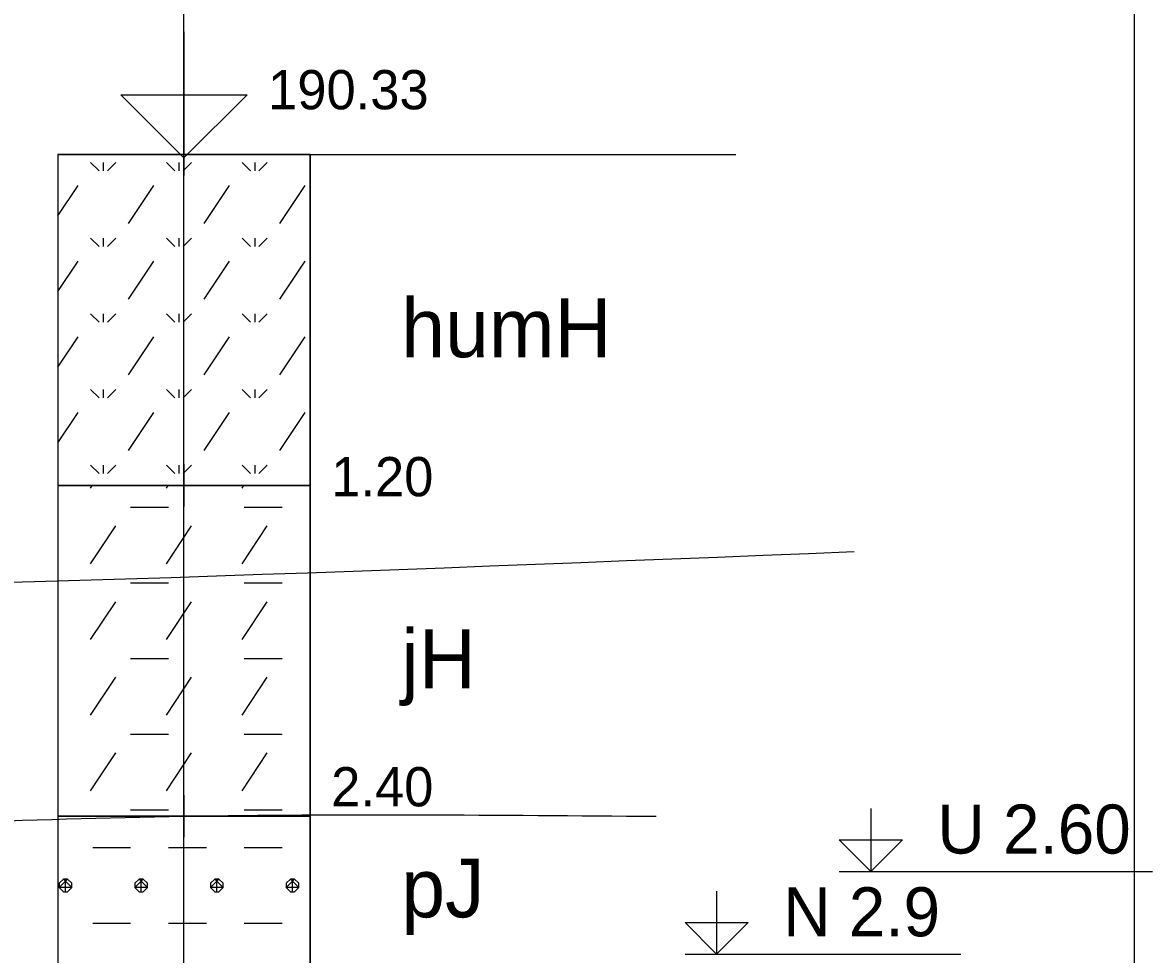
# Model space of a CAD drawing. Extents: x 3042 to 4120, y 576 to 2694.
# Drawn here: x 3544.97 to 3565.44, y 1293.69 to 1310.59 of the extents above; entities that cross this region are included whole.
import ezdxf

# ---------------------------------------------------------------- set-up
doc = ezdxf.new("R2010")
doc.units = 0
for name, color, linetype in [('11', 7, 'Continuous'), ('15', 7, 'Continuous'), ('17', 7, 'Continuous'), ('18', 7, 'Continuous'), ('51', 7, 'Continuous'), ('52', 7, 'Continuous'), ('53', 7, 'Continuous'), ('56', 7, 'Continuous'), ('61', 7, 'Continuous'), ('pomocna', 7, 'Continuous'), ('rozhraní', 7, 'Continuous')]:
    doc.layers.add(name, color=color, linetype=linetype)

msp = doc.modelspace()

# ---------------------------------------------------------------- linework, layer by layer
at = {"layer": '11'}
msp.add_line((3547.897, 1308.195), (3557.897, 1308.195), dxfattribs=at)
at = {"layer": '15'}
msp.add_lwpolyline([(3547.897, 1310.418), (3547.897, 1308.132), (3546.754, 1309.275), (3549.04, 1309.275), (3547.897, 1308.132)], dxfattribs=at)
msp.add_lwpolyline([(3547.897, 1310.418), (3547.897, 1308.132), (3546.754, 1309.275), (3549.04, 1309.275), (3547.897, 1308.132)], dxfattribs=at)
at = {"layer": '18'}
msp.add_line((3547.897, 1265.195), (3547.897, 1308.195), dxfattribs=at)
at = {"layer": '51'}
for p, q in [((3546.206, 1308.049), (3546.359, 1307.897)), ((3546.435, 1308.049), (3546.435, 1307.897)), ((3546.663, 1308.049), (3546.511, 1307.897)), ((3547.578, 1308.049), (3547.73, 1307.897)), ((3547.806, 1308.049), (3547.806, 1307.897)), ((3548.035, 1308.049), (3547.883, 1307.897)), ((3548.949, 1308.049), (3549.102, 1307.897)), ((3549.178, 1308.049), (3549.178, 1307.897)), ((3549.407, 1308.049), (3549.254, 1307.897)), ((3545.611, 1307.08), (3545.978, 1307.63)), ((3546.892, 1306.944), (3547.349, 1307.63)), ((3548.264, 1306.944), (3548.721, 1307.63)), ((3549.635, 1306.944), (3550.092, 1307.63)), ((3546.206, 1306.678), (3546.359, 1306.525)), ((3546.435, 1306.678), (3546.435, 1306.525)), ((3546.663, 1306.678), (3546.511, 1306.525)), ((3547.578, 1306.678), (3547.73, 1306.525)), ((3547.806, 1306.678), (3547.806, 1306.525)), ((3548.035, 1306.678), (3547.883, 1306.525)), ((3548.949, 1306.678), (3549.102, 1306.525)), ((3549.178, 1306.678), (3549.178, 1306.525)), ((3549.407, 1306.678), (3549.254, 1306.525)), ((3545.611, 1305.708), (3545.978, 1306.258)), ((3546.892, 1305.573), (3547.349, 1306.258)), ((3548.264, 1305.573), (3548.721, 1306.258)), ((3549.635, 1305.573), (3550.092, 1306.258)), ((3546.206, 1305.306), (3546.359, 1305.154)), ((3546.435, 1305.306), (3546.435, 1305.154)), ((3546.663, 1305.306), (3546.511, 1305.154)), ((3547.578, 1305.306), (3547.73, 1305.154)), ((3547.806, 1305.306), (3547.806, 1305.154)), ((3548.035, 1305.306), (3547.883, 1305.154)), ((3548.949, 1305.306), (3549.102, 1305.154)), ((3549.178, 1305.306), (3549.178, 1305.154)), ((3549.407, 1305.306), (3549.254, 1305.154)), ((3545.611, 1304.337), (3545.978, 1304.887)), ((3546.892, 1304.201), (3547.349, 1304.887)), ((3548.264, 1304.201), (3548.721, 1304.887)), ((3549.635, 1304.201), (3550.092, 1304.887)), ((3546.206, 1303.934), (3546.359, 1303.782)), ((3546.435, 1303.934), (3546.435, 1303.782)), ((3546.663, 1303.934), (3546.511, 1303.782)), ((3547.578, 1303.934), (3547.73, 1303.782)), ((3547.806, 1303.934), (3547.806, 1303.782)), ((3548.035, 1303.934), (3547.883, 1303.782)), ((3548.949, 1303.934), (3549.102, 1303.782)), ((3549.178, 1303.934), (3549.178, 1303.782)), ((3549.407, 1303.934), (3549.254, 1303.782)), ((3545.611, 1302.965), (3545.978, 1303.515)), ((3546.892, 1302.829), (3547.349, 1303.515)), ((3548.264, 1302.829), (3548.721, 1303.515)), ((3549.635, 1302.829), (3550.092, 1303.515)), ((3546.206, 1302.563), (3546.359, 1302.41)), ((3546.435, 1302.563), (3546.435, 1302.41)), ((3546.663, 1302.563), (3546.511, 1302.41)), ((3547.578, 1302.563), (3547.73, 1302.41)), ((3547.806, 1302.563), (3547.806, 1302.41)), ((3548.035, 1302.563), (3547.883, 1302.41)), ((3548.949, 1302.563), (3549.102, 1302.41)), ((3549.178, 1302.563), (3549.178, 1302.41)), ((3549.407, 1302.563), (3549.254, 1302.41)), ((3546.206, 1302.144), (3546.241, 1302.196)), ((3547.578, 1302.144), (3547.612, 1302.195)), ((3548.949, 1302.144), (3548.984, 1302.195)), ((3546.93, 1301.801), (3547.616, 1301.801)), ((3548.988, 1301.801), (3549.673, 1301.801)), ((3546.206, 1300.772), (3546.663, 1301.458)), ((3547.578, 1300.772), (3548.035, 1301.458)), ((3548.949, 1300.772), (3549.407, 1301.458)), ((3546.93, 1300.429), (3547.616, 1300.429)), ((3548.988, 1300.429), (3549.673, 1300.429)), ((3546.206, 1299.4), (3546.663, 1300.086)), ((3547.578, 1299.4), (3548.035, 1300.086)), ((3548.949, 1299.4), (3549.407, 1300.086)), ((3546.93, 1299.058), (3547.616, 1299.058)), ((3548.988, 1299.058), (3549.673, 1299.058)), ((3546.206, 1298.029), (3546.663, 1298.715)), ((3547.578, 1298.029), (3548.035, 1298.715)), ((3548.949, 1298.029), (3549.407, 1298.715)), ((3546.93, 1297.686), (3547.616, 1297.686)), ((3548.988, 1297.686), (3549.673, 1297.686)), ((3546.206, 1296.657), (3546.663, 1297.343)), ((3547.578, 1296.657), (3548.035, 1297.343)), ((3548.949, 1296.657), (3549.407, 1297.343)), ((3546.93, 1296.314), (3547.616, 1296.314)), ((3548.988, 1296.314), (3549.673, 1296.314)), ((3546.244, 1295.629), (3546.93, 1295.629)), ((3547.616, 1295.629), (3548.302, 1295.629)), ((3548.988, 1295.629), (3549.673, 1295.629)), ((3545.749, 1294.828), (3545.749, 1295.057)), ((3547.121, 1294.828), (3547.121, 1295.057)), ((3548.492, 1294.828), (3548.492, 1295.057)), ((3549.864, 1294.828), (3549.864, 1295.057)), ((3546.244, 1294.257), (3546.93, 1294.257)), ((3547.616, 1294.257), (3548.302, 1294.257)), ((3548.988, 1294.257), (3549.673, 1294.257))]:
    msp.add_line(p, q, dxfattribs=at)
for points in [[(3545.611, 1302.195), (3550.183, 1302.195), (3550.183, 1308.195), (3545.611, 1308.195)], [(3545.611, 1296.195), (3550.183, 1296.195), (3550.183, 1302.195), (3545.611, 1302.195)], [(3545.611, 1291.945), (3550.183, 1291.945), (3550.183, 1296.195), (3545.611, 1296.195)]]:
    msp.add_lwpolyline(points, close=True, dxfattribs=at)
for points in [[(3545.711, 1295.057), (3545.635, 1294.981), (3545.635, 1294.905), (3545.711, 1294.828), (3545.787, 1294.828), (3545.863, 1294.905), (3545.863, 1294.981), (3545.787, 1295.057), (3545.711, 1295.057), (3545.863, 1294.905), (3545.635, 1294.905), (3545.787, 1295.057)], [(3547.083, 1295.057), (3547.006, 1294.981), (3547.006, 1294.905), (3547.083, 1294.828), (3547.159, 1294.828), (3547.235, 1294.905), (3547.235, 1294.981), (3547.159, 1295.057), (3547.083, 1295.057), (3547.235, 1294.905), (3547.006, 1294.905), (3547.159, 1295.057)], [(3548.454, 1295.057), (3548.378, 1294.981), (3548.378, 1294.905), (3548.454, 1294.828), (3548.53, 1294.828), (3548.607, 1294.905), (3548.607, 1294.981), (3548.53, 1295.057), (3548.454, 1295.057), (3548.607, 1294.905), (3548.378, 1294.905), (3548.53, 1295.057)], [(3549.826, 1295.057), (3549.75, 1294.981), (3549.75, 1294.905), (3549.826, 1294.828), (3549.902, 1294.828), (3549.978, 1294.905), (3549.978, 1294.981), (3549.902, 1295.057), (3549.826, 1295.057), (3549.978, 1294.905), (3549.75, 1294.905), (3549.902, 1295.057)]]:
    msp.add_lwpolyline(points, dxfattribs=at)
at = {"layer": '53'}
for p, q in [((3545.611, 1308.195), (3550.183, 1308.195)), ((3545.611, 1308.195), (3545.611, 1265.195)), ((3550.183, 1308.195), (3550.183, 1265.195)), ((3545.611, 1302.195), (3550.183, 1302.195)), ((3545.611, 1296.195), (3550.183, 1296.195))]:
    msp.add_line(p, q, dxfattribs=at)
at = {"layer": '56'}
for p, q in [((3547.897, 1308.576), (3547.897, 1307.814)), ((3547.516, 1308.195), (3548.278, 1308.195)), ((3547.897, 1302.576), (3547.897, 1301.814)), ((3547.516, 1302.195), (3548.278, 1302.195)), ((3547.897, 1296.576), (3547.897, 1295.814)), ((3547.516, 1296.195), (3548.278, 1296.195))]:
    msp.add_line(p, q, dxfattribs=at)
at = {"layer": '61'}
for p, q in [((3559.77, 1295.195), (3565.443, 1295.195)), ((3556.976, 1293.695), (3561.972, 1293.695))]:
    msp.add_line(p, q, dxfattribs=at)
for points in [[(3560.342, 1296.338), (3560.342, 1295.195), (3559.77, 1295.767), (3560.913, 1295.767), (3560.342, 1295.195)], [(3557.548, 1294.838), (3557.548, 1293.695), (3556.976, 1294.267), (3558.119, 1294.267), (3557.548, 1293.695)]]:
    msp.add_lwpolyline(points, dxfattribs=at)
at = {"layer": 'pomocna'}
for p, q in [((3565.117, 1251.545), (3565.117, 1314.895)), ((3547.897, 1251.545), (3547.897, 1313.195))]:
    msp.add_line(p, q, dxfattribs=at)
at = {"layer": 'rozhraní'}
for points in [[(3215.367, 1295.492), (3223.007, 1295.445), (3284.237, 1298.745), (3466.926, 1305.295), (3469.69, 1305.295), (3507.357, 1301.345), (3560.04, 1300.995)], [(3271.345, 1282.999), (3284.237, 1284.245), (3297.343, 1284.894), (3310.501, 1285.162), (3323.62, 1285.371), (3336.607, 1285.845), (3347.74, 1287.702), (3358.827, 1290.97), (3369.9, 1294.05), (3375.439, 1295.021), (3378.212, 1295.276), (3380.987, 1295.345), (3390.374, 1294.201), (3399.75, 1291.756), (3409.16, 1289.169), (3418.647, 1287.595), (3430.693, 1286.786), (3442.786, 1286.102), (3454.9, 1285.59), (3467.007, 1285.295), (3487.184, 1285.301), (3497.273, 1285.651), (3507.357, 1286.345), (3512.194, 1287.141), (3526.536, 1295.496), (3547.897, 1291.945), (3557.186, 1291.945)], [(3530.901, 1295.341), (3547.897, 1296.195), (3556.45, 1296.195)]]:
    msp.add_spline(points, degree=3, dxfattribs=at)

# ---------------------------------------------------------------- texts
at = {"layer": '17'}
msp.add_text('190.33', height=0.7112, dxfattribs=at).set_placement((3549.421, 1309.013))
at = {"layer": '52'}
for s, height, p in [('humH', 1.0668, (3551.834, 1304.517)), ('1.20', 0.7112, (3550.564, 1301.997)), ('jH', 1.0668, (3551.834, 1298.517)), ('2.40', 0.7112, (3550.564, 1296.375)), ('pJ', 1.0668, (3551.834, 1294.362))]:
    msp.add_text(s, height=height, dxfattribs=at).set_placement(p)
at = {"layer": '61'}
for s, p in [('U 2.60', (3561.548, 1295.519)), ('N 2.9', (3558.754, 1294.019))]:
    msp.add_text(s, height=0.889, dxfattribs=at).set_placement(p)

doc.saveas('drawing.dxf')
